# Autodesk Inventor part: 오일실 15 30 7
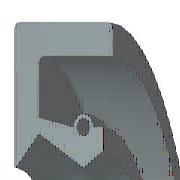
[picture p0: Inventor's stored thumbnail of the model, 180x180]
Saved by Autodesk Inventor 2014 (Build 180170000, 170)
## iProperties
IsCustomPart: 1
Created: 2012-02
Part Number: 오일실 15 30 7
Material: 고무
Description: 오일-실
Document SubType Name: Modeling
Standard: KS B 2804
Designer: mduedu
Standards Organization: KS
Language: ko-KR
Size Designation: D - 15 30 7
Categories: <MemberInstance><Categories><Category DisplayName="샤프트 부품" InternalName="7f7aeb1f-a693-4053-b835-cee3144e0d98" Mnemonic="SHFT"><Category DisplayName="실링" Intern
Density: 0.93 g/cm^3
Appearance: 고무 - 검은색 - 버전 1.1
Author: mduedu
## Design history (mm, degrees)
revolve "본체" stored, may be unused: angle "d17" = 90 deg
revolve "스프링1" stored, may be unused: angle "d18" = 90 deg
body "Solid1"
sketch "스케치1"
  geometry: L1 (0, 15)-(7, 15); L2 (7, 13.25)-(1.75, 13.25); L3 (1.75, 9.25)-(4.9, 7.5); L4 (4.9, 7.5)-(0, 7.5); L5 (0, 0)-(9.586, 0) reference; L6 (4.9, 7.5)-(6.3, 8.375); L7 (0, 18)-(0, -3) reference; L8 (-1.941, 0)-(11.507, 0) reference; L9 (4.2, 9.6)-(1.75, 10.09); L10 (1.75, 10.09)-(1.75, 13.25); L11 (0, 15)-(0, 7.588); L12 (4.9, 7.5)-(0, 7.5); L13 (1.75, 9.25)-(0.152, 7.528); L14 (7, 15)-(7, 13.25); L15 (5.6, 9.6)-(6.3, 9.6); L16 (6.3, 9.6)-(6.3, 8.375); C1 r 0.455 at (4.9, 9.6); A1 r 0.7 centre (4.9, 9.6) between (5.6, 9.6) and (4.2, 9.6); A2 r 0.088 centre (0.088, 7.588) between (0, 7.588) and (0.152, 7.528); 1 further point
  constraints: 28 end point, 5 horizontal alignment, 5 point on line, 4 point on circle, 4 vertical alignment, 3 centre point, 3 tangent, 2 collinear, 2 horizontal, 2 perpendicular, 1 coincident, 1 parallel
  dimensions: "d0" = 30 diameter of L1 L5 (= SD2); "d1" = 1.75 distance of L1.end L2.start (= SD); "d2" = 0.91 diameter of C1 (= SPDI); "d3" = 1.4 diameter of A1 (= SPDA); "d4" = 15 diameter of L3.end L5 (= NND); "d5" = 18.5 diameter of L3.start L5 (= TKDM); "d7" = 20.18 diameter of L9.end L5 (= TKDM + 0.24 x SWDT); "d8" = 1.75 distance between parallel lines of L11 L10 (= SD); "d9" = 4.9 distance from line of L11 C1.centre (= SPDST); "d10" = 19.2 diameter of C1.centre L5 (= HLDM); "d11" = 0.0875 radius of A2 (= 0.25 x LAB); "d12" = 6.3 distance between parallel lines of L11 L16 (= SDI); "d13" = 16.75 diameter of L6.end L5 (= ABDM); "d14" = 7 distance from line of L11 L1.end (= SWDT)
fillet "모깎기1" dims "d6" = 0.3 (= RR)
other parameters: "SD2" = 30 [user parameter; used in 1 equation term], "SWDT" = 7 [user parameter; used in 2 equation terms], "RR" = 0.3 [user parameter; used in 1 equation term], "SD" = 1.75 [user parameter; used in 2 equation terms], "NND" = 15 [user parameter; used in 1 equation term], "SPDA" = 1.4 [user parameter; used in 1 equation term], "SPDI" = 0.91 [user parameter; used in 1 equation term], "TKDM" = 18.5 [user parameter; used in 2 equation terms], "HLDM" = 19.2 [user parameter; used in 1 equation term], "ABDM" = 16.75 [user parameter; used in 1 equation term], "SDI" = 6.3 [user parameter; used in 1 equation term], "SPDST" = 4.9 [user parameter; used in 1 equation term], "LAB" = 0.35 [user parameter; used in 1 equation term], "d15" = 0, "d16" = 0, "d19" = 0
